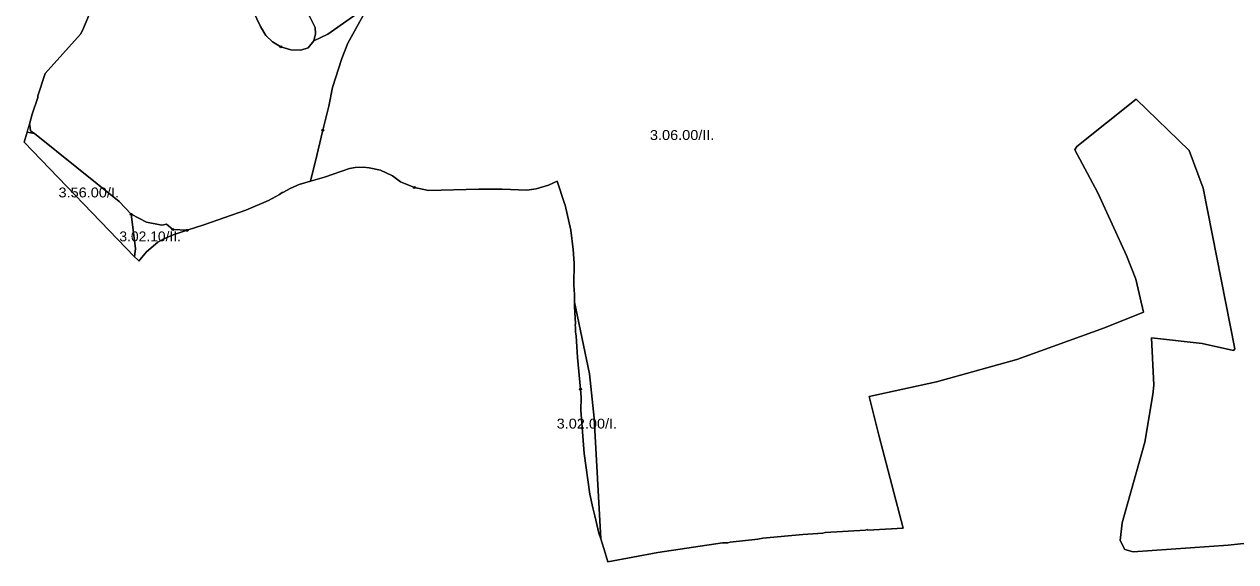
# Model space of a CAD drawing. Extents: x -650455 to -642254, y -1075222 to -1066610.
# Drawn here: x -645645 to -644416, y -1073659 to -1073114 of the extents above; entities that cross this region are included whole.
import ezdxf
from ezdxf.enums import TextEntityAlignment as Align

# ---------------------------------------------------------------- set-up
doc = ezdxf.new("R2010")
doc.units = 0
doc.header["$LTSCALE"] = 4
doc.header["$PDMODE"] = 32
doc.header["$PDSIZE"] = 2
for name, color, linetype, lineweight in [('1', 7, 'Continuous', 25), ('11', 7, 'Continuous', 13), ('12', 7, 'Continuous', 13), ('13', 7, 'Continuous', 13), ('14', 7, 'Continuous', 13)]:
    doc.layers.add(name, color=color, linetype=linetype, lineweight=lineweight)
doc.layers.add('2', color=7, linetype='Continuous')

msp = doc.modelspace()

# ---------------------------------------------------------------- linework, layer by layer
at = {"layer": '1'}
for points in [[(-645351.243, -1073131.207), (-645357.013, -1073138.376), (-645364.358, -1073140.474), (-645374.499, -1073140.125), (-645384.641, -1073137.152), (-645393.034, -1073132.256), (-645399.679, -1073125.611), (-645405.274, -1073116.694), (-645412.618, -1073101.131), (-645418.563, -1073077.351), (-645423.109, -1073054.795), (-645415.59, -1073061.089), (-645393.558, -1073075.428), (-645375.373, -1073085.744), (-645364.532, -1073094.137), (-645360.161, -1073098.159), (-645354.74, -1073107.426), (-645349.844, -1073117.568), (-645349.32, -1073124.038)], [(-645638.532, -1073222.307), (-645634.5, -1073225.001), (-645641.977, -1073223.681), (-645639.672, -1073215.65), (-645639.079, -1073216.724)], [(-645532, -1073341.501), (-645532.942, -1073349.981), (-645644.929, -1073233.97), (-645641.977, -1073223.681), (-645634.5, -1073225.001), (-645548.5, -1073294.001), (-645536.5, -1073307)], [(-645382.453, -1073284.826), (-645386.001, -1073286.755), (-645383.329, -1073284.731)], [(-645521, -1073315), (-645505.5, -1073318.001), (-645500.597, -1073317.109), (-645494.276, -1073322.5), (-645479.792, -1073323.208), (-645493.898, -1073327.697), (-645503.277, -1073331.676), (-645509.529, -1073335.37), (-645520.898, -1073344.89), (-645527.577, -1073353.132), (-645528.504, -1073354.578), (-645530.085, -1073352.941), (-645532.942, -1073349.981), (-645532, -1073341.501), (-645536.5, -1073307)], [(-645060.1, -1073635.952), (-645061.878, -1073630.295), (-645065.97, -1073612.516), (-645068.228, -1073604.614), (-645071.191, -1073590.784), (-645076.977, -1073549.296), (-645080.222, -1073505.551), (-645080.081, -1073492.851), (-645080.505, -1073484.384), (-645083.609, -1073452.21), (-645085.02, -1073430.198), (-645085.585, -1073426.529), (-645085.585, -1073421.449), (-645086.149, -1073419.472), (-645085.867, -1073417.78), (-645086.714, -1073400.563), (-645086.714, -1073396.177), (-645071.473, -1073468.855), (-645066.839, -1073513.793)]]:
    msp.add_lwpolyline(points, close=True, dxfattribs=at)
for points in [[(-645322.654, -1073149.042), (-645332.097, -1073178.418), (-645335.943, -1073197.478), (-645342.151, -1073221.608), (-645349.757, -1073254.306), (-645354.478, -1073273.19), (-645354.488, -1073273.432), (-645366.002, -1073276.823), (-645374.529, -1073280.517), (-645382.453, -1073284.826), (-645383.329, -1073284.731), (-645386.001, -1073286.755), (-645397.266, -1073292.881), (-645420.003, -1073302.828), (-645462.634, -1073317.748), (-645479.792, -1073323.208), (-645494.276, -1073322.5), (-645500.597, -1073317.109), (-645505.5, -1073318.001), (-645521, -1073315), (-645536.5, -1073307), (-645548.5, -1073294.001), (-645634.5, -1073225.001), (-645638.532, -1073222.307), (-645639.079, -1073216.724), (-645639.672, -1073215.65), (-645636.773, -1073205.545), (-645631.269, -1073188.612), (-645631.128, -1073186.919), (-645623.649, -1073164.198), (-645587.806, -1073124.405), (-645585.831, -1073120.596), (-645576.8, -1073098.864)], [(-645412.618, -1073101.131), (-645405.274, -1073116.694), (-645399.679, -1073125.611), (-645393.034, -1073132.256), (-645384.641, -1073137.152), (-645374.499, -1073140.125), (-645364.358, -1073140.474), (-645357.013, -1073138.376), (-645351.243, -1073131.207), (-645336.905, -1073124.213), (-645294.852, -1073094.837)], [(-645294.852, -1073094.837), (-645336.905, -1073124.213), (-645351.243, -1073131.207), (-645349.32, -1073124.038), (-645349.844, -1073117.568), (-645354.74, -1073107.426)], [(-645086.714, -1073396.177), (-645086.714, -1073388.427), (-645087.278, -1073378.832), (-645086.996, -1073356.537), (-645088.125, -1073342.708), (-645090.524, -1073322.952), (-645096.027, -1073297.551), (-645096.874, -1073295.999), (-645104.297, -1073273.411), (-645113.053, -1073277.391), (-645125.558, -1073281.086), (-645134.938, -1073282.648), (-645159.948, -1073281.511), (-645183.822, -1073281.511), (-645234.98, -1073282.791), (-645249.191, -1073279.665), (-645263.402, -1073273.98), (-645271.501, -1073267.869), (-645283.581, -1073262.328), (-645294.949, -1073259.77), (-645300.633, -1073259.2), (-645309.16, -1073259.627), (-645314.844, -1073260.48), (-645340.423, -1073269.29), (-645354.488, -1073273.432), (-645354.478, -1073273.19), (-645349.757, -1073254.306), (-645342.151, -1073221.608), (-645335.943, -1073197.478), (-645332.097, -1073178.418), (-645322.654, -1073149.042), (-645316.797, -1073133.48), (-645301.06, -1073105.503)], [(-645301.06, -1073105.503), (-645316.797, -1073133.48), (-645322.654, -1073149.042)], [(-644508.15, -1073538.007), (-644499.965, -1073489.748), (-644499.118, -1073480.04), (-644501.498, -1073432.196), (-644450.153, -1073438.099), (-644418.12, -1073445.155), (-644416.85, -1073443.462), (-644449.165, -1073280.335), (-644463.276, -1073242.235), (-644516.891, -1073190.139), (-644577.295, -1073238.143), (-644579.271, -1073241.528), (-644555.705, -1073285.133), (-644526.918, -1073348.634), (-644517.463, -1073372.622), (-644509.633, -1073406.043), (-644549.004, -1073422.171), (-644638.115, -1073454.186), (-644719.397, -1073476.905), (-644787.865, -1073491.654), (-644778.163, -1073530.809), (-644753.225, -1073625.103), (-644789.247, -1073627.05), (-644789.812, -1073626.485), (-644791.646, -1073627.05), (-644832.287, -1073629.59), (-644834.827, -1073630.155), (-644855.147, -1073631.566), (-644895.788, -1073635.376), (-644900.868, -1073636.223), (-644928.808, -1073639.185), (-644931.348, -1073639.89), (-644936.429, -1073640.033), (-645002.046, -1073649.911), (-645052.793, -1073659.198), (-645055.646, -1073650.122), (-645060.1, -1073635.952), (-645066.839, -1073513.793), (-645071.473, -1073468.855), (-645086.714, -1073396.177)], [(-644376.209, -1073637.35), (-644423.623, -1073642.431), (-644520.145, -1073649.204), (-644528.329, -1073646.806), (-644533.268, -1073637.633), (-644531.151, -1073619.854), (-644508.15, -1073538.007)]]:
    msp.add_lwpolyline(points, dxfattribs=at)
at = {"layer": '11'}
for points in [[(-645536.5, -1073307), (-645548.5, -1073294.001), (-645634.5, -1073225.001), (-645641.977, -1073223.681), (-645644.929, -1073233.97), (-645532.942, -1073349.981)], [(-645532.942, -1073349.981), (-645532, -1073341.501), (-645536.5, -1073307)]]:
    msp.add_lwpolyline(points, dxfattribs=at)
msp.add_lwpolyline([(-645080.505, -1073484.384), (-645080.081, -1073492.851), (-645080.222, -1073505.551), (-645076.977, -1073549.296), (-645071.191, -1073590.784), (-645068.228, -1073604.614), (-645065.97, -1073612.516), (-645061.878, -1073630.295), (-645060.1, -1073635.952), (-645066.839, -1073513.793), (-645071.473, -1073468.855), (-645086.714, -1073396.177), (-645086.714, -1073400.563), (-645085.867, -1073417.78), (-645086.149, -1073419.472), (-645085.585, -1073421.449), (-645085.585, -1073426.529), (-645085.02, -1073430.198), (-645083.609, -1073452.21)], close=True, dxfattribs=at)
for p in [(-645536.5, -1073307), (-645080.505, -1073484.384)]:
    msp.add_point(p, dxfattribs=at)
at = {"layer": '12'}
for points in [[(-645301.06, -1073105.503), (-645316.797, -1073133.48), (-645322.654, -1073149.042), (-645332.097, -1073178.418), (-645335.943, -1073197.478), (-645342.151, -1073221.608), (-645349.757, -1073254.306), (-645354.478, -1073273.19), (-645354.488, -1073273.432), (-645340.423, -1073269.29), (-645314.844, -1073260.48), (-645309.16, -1073259.627), (-645300.633, -1073259.2), (-645294.949, -1073259.77), (-645283.581, -1073262.328), (-645271.501, -1073267.869), (-645263.402, -1073273.98), (-645249.191, -1073279.665)], [(-644509.633, -1073406.043), (-644517.463, -1073372.622), (-644526.918, -1073348.634), (-644555.705, -1073285.133), (-644579.271, -1073241.528), (-644577.295, -1073238.143), (-644516.891, -1073190.139), (-644463.276, -1073242.235), (-644449.165, -1073280.335), (-644416.85, -1073443.462), (-644418.12, -1073445.155), (-644450.153, -1073438.099), (-644501.498, -1073432.196), (-644499.118, -1073480.04), (-644499.965, -1073489.748), (-644508.15, -1073538.007), (-644531.151, -1073619.854), (-644533.268, -1073637.633), (-644528.329, -1073646.806), (-644520.145, -1073649.204), (-644423.623, -1073642.431), (-644376.209, -1073637.35)], [(-645249.191, -1073279.665), (-645234.98, -1073282.791), (-645183.822, -1073281.511), (-645159.948, -1073281.511), (-645134.938, -1073282.648), (-645125.558, -1073281.086), (-645113.053, -1073277.391), (-645104.297, -1073273.411), (-645096.874, -1073295.999), (-645096.027, -1073297.551), (-645090.524, -1073322.952), (-645088.125, -1073342.708), (-645086.996, -1073356.537), (-645087.278, -1073378.832), (-645086.714, -1073388.427), (-645086.714, -1073396.177), (-645071.473, -1073468.855), (-645066.839, -1073513.793), (-645060.1, -1073635.952), (-645055.646, -1073650.122), (-645052.793, -1073659.198), (-645002.046, -1073649.911), (-644936.429, -1073640.033), (-644931.348, -1073639.89), (-644928.808, -1073639.185), (-644900.868, -1073636.223), (-644895.788, -1073635.376), (-644855.147, -1073631.566), (-644834.827, -1073630.155), (-644832.287, -1073629.59), (-644791.646, -1073627.05), (-644789.812, -1073626.485), (-644789.247, -1073627.05), (-644753.225, -1073625.103), (-644778.163, -1073530.809), (-644787.865, -1073491.654), (-644719.397, -1073476.905), (-644638.115, -1073454.186), (-644549.004, -1073422.171), (-644509.633, -1073406.043)], [(-645479.792, -1073323.208), (-645494.276, -1073322.5), (-645500.597, -1073317.109), (-645505.5, -1073318.001), (-645521, -1073315), (-645536.5, -1073307), (-645532, -1073341.501)], [(-645532, -1073341.501), (-645532.942, -1073349.981), (-645530.085, -1073352.941), (-645528.504, -1073354.578), (-645527.577, -1073353.132), (-645520.898, -1073344.89), (-645509.529, -1073335.37), (-645503.277, -1073331.676), (-645493.898, -1073327.697), (-645479.792, -1073323.208)]]:
    msp.add_lwpolyline(points, dxfattribs=at)
for p in [(-645249.191, -1073279.665), (-645479.792, -1073323.208)]:
    msp.add_point(p, dxfattribs=at)
at = {"layer": '13'}
for points in [[(-645342.151, -1073221.608), (-645335.943, -1073197.478), (-645332.097, -1073178.418), (-645322.654, -1073149.042), (-645316.797, -1073133.48), (-645301.06, -1073105.503), (-645294.852, -1073094.837), (-645336.905, -1073124.213), (-645351.243, -1073131.207), (-645357.013, -1073138.376), (-645364.358, -1073140.474), (-645374.499, -1073140.125), (-645384.641, -1073137.152), (-645393.034, -1073132.256), (-645399.679, -1073125.611), (-645405.274, -1073116.694), (-645412.618, -1073101.131), (-645418.563, -1073077.351), (-645423.109, -1073054.795), (-645433.338, -1073026.118), (-645442.606, -1073007.758)], [(-645375.373, -1073085.744), (-645364.532, -1073094.137), (-645360.161, -1073098.159), (-645354.74, -1073107.426), (-645349.844, -1073117.568), (-645349.32, -1073124.038), (-645351.243, -1073131.207), (-645336.905, -1073124.213), (-645294.852, -1073094.837)], [(-645576.8, -1073098.864), (-645585.831, -1073120.596), (-645587.806, -1073124.405), (-645623.649, -1073164.198), (-645631.128, -1073186.919), (-645631.269, -1073188.612), (-645636.773, -1073205.545), (-645639.672, -1073215.65), (-645639.079, -1073216.724), (-645638.532, -1073222.307), (-645634.5, -1073225.001), (-645548.5, -1073294.001), (-645536.5, -1073307), (-645521, -1073315), (-645505.5, -1073318.001), (-645500.597, -1073317.109), (-645494.276, -1073322.5)], [(-645494.276, -1073322.5), (-645479.792, -1073323.208), (-645462.634, -1073317.748), (-645420.003, -1073302.828), (-645397.266, -1073292.881), (-645386.001, -1073286.755), (-645383.329, -1073284.731), (-645382.453, -1073284.826), (-645374.529, -1073280.517), (-645366.002, -1073276.823), (-645354.488, -1073273.432), (-645354.478, -1073273.19), (-645349.757, -1073254.306), (-645342.151, -1073221.608)]]:
    msp.add_lwpolyline(points, dxfattribs=at)
for p in [(-645342.151, -1073221.608), (-645494.276, -1073322.5)]:
    msp.add_point(p, dxfattribs=at)
at = {"layer": '14'}
for points in [[(-645364.532, -1073094.137), (-645375.373, -1073085.744), (-645393.558, -1073075.428), (-645415.59, -1073061.089), (-645423.109, -1073054.795), (-645418.563, -1073077.351), (-645412.618, -1073101.131), (-645405.274, -1073116.694), (-645399.679, -1073125.611), (-645393.034, -1073132.256), (-645384.641, -1073137.152)], [(-645384.641, -1073137.152), (-645374.499, -1073140.125), (-645364.358, -1073140.474), (-645357.013, -1073138.376), (-645351.243, -1073131.207), (-645349.32, -1073124.038), (-645349.844, -1073117.568), (-645354.74, -1073107.426), (-645360.161, -1073098.159), (-645364.532, -1073094.137)]]:
    msp.add_lwpolyline(points, dxfattribs=at)
msp.add_point((-645384.641, -1073137.152), dxfattribs=at)

# ---------------------------------------------------------------- texts
at = {"layer": '2'}
for s, width, p in [('3.06.00/II.', 1.1, (-644977.478, -1073231.6)), ('3.56.00/I.', 1.1, (-645579.497, -1073289.837)), ('3.02.10/II.', 1.05, (-645517.168, -1073334.373)), ('3.02.00/I.', 1.1, (-645074.164, -1073524.163))]:
    msp.add_text(s, height=10, dxfattribs=dict(at, width=width)).set_placement(p, align=Align.CENTER)

doc.saveas('drawing.dxf')
